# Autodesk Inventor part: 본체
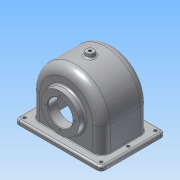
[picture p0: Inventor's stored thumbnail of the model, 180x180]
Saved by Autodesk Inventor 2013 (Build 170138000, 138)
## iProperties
Created: 2015-09
Part Number: 본체
Material: 알루미늄 6061
Document SubType Name: Modeling
Designer: Administrator
Density: 2.71 g/cm^3
Mass: 724.641 g
Surface Area: 889.989 cm^2
Volume: 267.395 cm^3
Author: Administrator
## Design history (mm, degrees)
sketch "스케치1"
  geometry: L1 (-57, 57)-(57, 57); L2 (57, 57)-(57, -47); L3 (57, -47)-(-57, -47); L4 (-57, -47)-(-57, 57); 2 further points
  constraints: 8 end point, 2 parallel, 1 horizontal, 1 midpoint, 1 perpendicular, 1 vertical alignment
  dimensions: "d0" = 47 distance from line of L3 point (0, 0); "d1" = 104 distance of L1.end L2.end; "d2" = 114 distance of L2.end L3.end
extrude "돌출1" new body sketch "스케치1" stored distance "d3" = 77; taper "d4" = 0 deg
node "작업 평면1"
sketch "스케치2"
  geometry: L1 (-70, 52)-(70, 52); L2 (70, 52)-(70, -52); L3 (70, -52)-(-70, -52); L4 (-70, -52)-(-70, 52); L5 (51, 33.5)-(-51, 33.5); L6 (-51, 33.5)-(-51, -33.5); L7 (-51, -33.5)-(51, -33.5); L8 (51, -33.5)-(51, 33.5); 5 further points
  constraints: 16 end point, 4 midpoint, 4 parallel, 2 horizontal, 2 horizontal alignment, 2 perpendicular, 2 vertical alignment
  dimensions: "d6" = 140 distance of L2.end L3.end; "d8" = 104 distance of L3.end L1.start; "d9" = 102 distance of L5.start L5.end; "d10" = 67 distance of L7.end L5.start
extrude "돌출2" join sketch "스케치2" distance "d11" = 7; taper "d12" = 0 deg
extrude "돌출3" cut sketch "스케치2" distance "d13" = 98; taper "d14" = 0 deg
fillet "모깎기1" dims "d15" = 57, "d16" = 51
sketch "스케치8"
  geometry: C1 r 31 at (0, 0); A1 r 57 centre (0, 0) between (57, 0) and (-57, 0) reference
  constraints: 1 centre point, 1 coincident
  dimensions: "d57" = 62 diameter of C1
extrude "돌출7" join sketch "스케치8" distance "d59" = 10; taper "d60" = 0 deg
node "작업 평면4"
sketch "스케치6"
  geometry: C1 r 28 at (0, 0); 1 further point
  constraints: 1 centre point, 1 coincident
  dimensions: "d31" = 56 diameter of C1
extrude "돌출6" join sketch "스케치6" stored distance "d33" = 98; taper "d34" = 40 deg
sketch "스케치7"
  geometry: L1 (38.5, 57)-(38.5, 0) reference; L2 (19.5, 28)-(33.5, 39.747) reference; L3 (19.5, 28)-(19.5, -28) reference; L4 (38.5, 0)-(38.5, 37.416); L5 (38.5, 37.416)-(33.237, 33); L6 (33.237, 33)-(35.5, 33); L7 (35.5, 33)-(35.5, 0); L8 (35.5, 0)-(38.5, 0); 1 further point
  constraints: 10 end point, 3 perpendicular, 1 parallel, 1 point on line
  dimensions: "d35" = 16 distance between parallel lines of L7 L3; "d36" = 5 distance between parallel lines of L5 L2; "d37" = 33 distance between parallel lines of L8 L6
revolve "회전1" sketch "스케치7" stored, may be unused: angle "d38" = 90 deg
hole "구멍1" diameter "d41" = 40; stored, may be unused: countersink angle "d45" = 90 deg, drill point angle "d47" = 0 deg; dims "d39" = 10, "d40" = 10, "d42" = 6, "d43" = 4, "d44" = 2, "d46" = 17
hole "구멍3" diameter "d63" = 40; stored, may be unused: countersink angle "d67" = 90 deg, drill point angle "d69" = 0 deg; dims "d61" = 10, "d62" = 10, "d64" = 6, "d65" = 4, "d66" = 2, "d68" = 17
sketch "스케치9"
  geometry: C1 r 20 at (0, 0) reference; 1 further point
  constraints: 1 vertical alignment
  dimensions: "d70" = 28 distance of point (0, -28) C1.centre
hole "구멍4" sketch "스케치9" at (0, -28) diameter "d71" = 2.459; stored, may be unused: countersink angle "d75" = 90 deg, drill point angle "d77" = 118 deg; dims "d72" = 7, "d73" = 4, "d74" = 2, "d76" = 9
sketch "스케치10"
  geometry: C1 r 20 at (0, 0) reference; 1 further point
  constraints: 1 vertical alignment
  dimensions: "d81" = 24 distance of point (0, 24) C1.centre
hole "구멍5" sketch "스케치10" at (0, 24) diameter "d82" = 2.459; stored, may be unused: countersink angle "d86" = 90 deg, drill point angle "d88" = 118 deg; dims "d83" = 6, "d84" = 4, "d85" = 2, "d87" = 8
node "작업 평면5"
sketch "스케치11"
  geometry: C1 r 6 at (0, 0); 1 further point
  constraints: 1 centre point, 1 coincident
  dimensions: "d93" = 12 diameter of C1
extrude "돌출8" join sketch "스케치11" stored distance "d95" = 10; taper "d96" = 10 deg
hole "구멍6" diameter "d99" = 4.459; stored, may be unused: countersink angle "d103" = 90 deg, drill point angle "d105" = 118 deg; dims "d97" = 10, "d98" = 10, "d100" = 20, "d101" = 4, "d102" = 2, "d104" = 8
sketch "스케치12"
  geometry: 4 further points
  constraints: 2 vertical alignment
  dimensions: "d106" = 62 distance of point (0, 0) point (-62, 0); "d107" = 44 distance of point (-62, 44) point (-62, 0); "d108" = 44 distance of point (-62, -44) point (-62, 0)
hole "구멍7" sketch "스케치12" at (-62, 44), (-62, 0), (-62, -44) diameter "d109" = 5; stored, may be unused: countersink angle "d113" = 90 deg, drill point angle "d115" = 0 deg; dims "d110" = 20, "d111" = 4, "d112" = 2, "d114" = 8
fillet "모깎기2" dims "d116" = 14, "d117" = 9, "d118" = 7, "d119" = 3
fillet "모깎기3" dims "d120" = 1, "d127" = 0.5
chamfer "모따기1" distance "d121" = 1; stored, may be unused: second distance "d122" = 2, angle "d123" = 45 deg
sketch "스케치13"
  geometry: L1 (0, 49)-(0, 0) reference; L2 (-47, 49)-(-47, 0) reference; 3 further points
  constraints: 1 horizontal alignment, 1 midpoint, 1 other
  dimensions: "d124" = 30 distance from line of L2 point (-17, 24.5)
feature "엠보싱1" sketch "스케치13" dims "d0" = 47, "d1" = 104, "d2" = 114, "d13" = 98, "d125" = 0.5, "d126" = 0
node "솔리드1"
pattern_circular "원형 패턴1" dims angle "d79" = 360 deg
pattern_circular "원형 패턴2" dims angle "d90" = 360 deg
mirror "대칭1"
other parameters: "d5" = -47, "d30" = -19, "d92" = 63
